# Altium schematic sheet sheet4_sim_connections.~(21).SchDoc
size A3; Author: Mauri Shadi; CompanyName: BFH; DrawnBy: Mauri Shadi; SheetNumber: 1; SheetTotal: 3
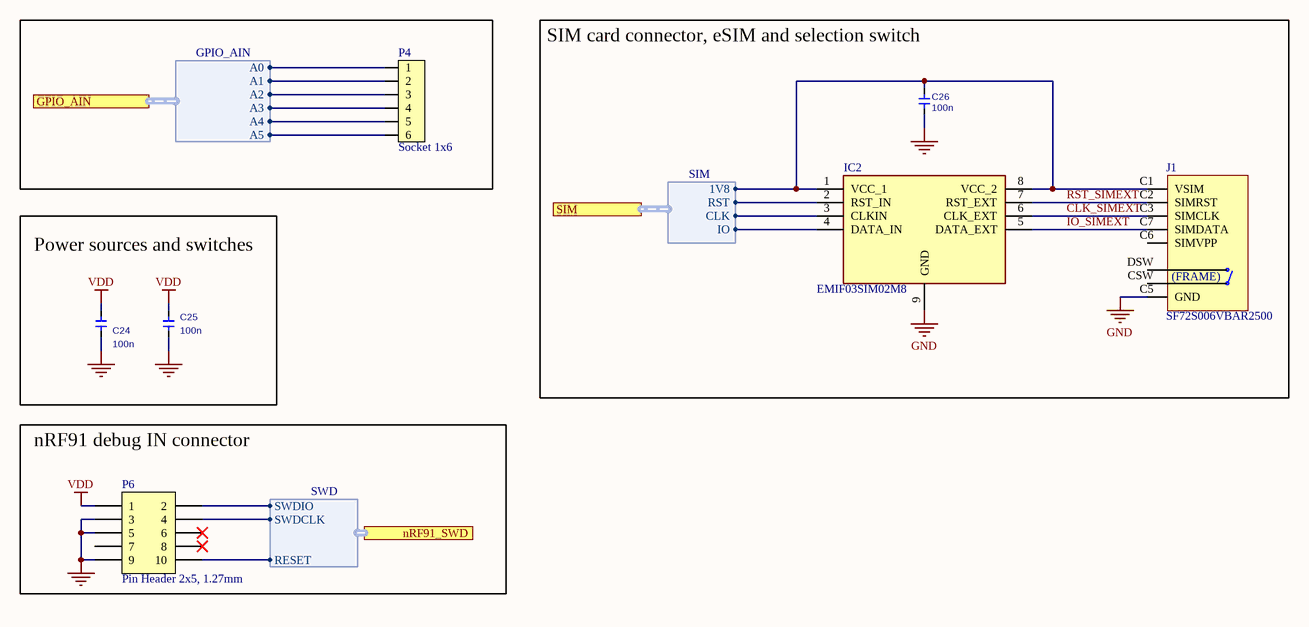
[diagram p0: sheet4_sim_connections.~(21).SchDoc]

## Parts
C24  100n  [0603(1608)C]
C25  100n  [0603(1608)C]
C26  100n  [0603(1608)C]
IC2  EMIF03SIM02M8  [SON40P150X170X60-9N-D]
J1  SF72S006VBAR2500  [SF72S006VBAR2500]
P4  Socket 1x6  [SOCKET_1x6_SMD]
P6  Pin Header 2x5, 1.27mm  [HDR_2x5-SMD-1.27mm-K]

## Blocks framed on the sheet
SIM card connector, eSIM and selection switch: C26 IC2 J1
Power sources and switches: C24 C25
nRF91 debug IN connector: P6

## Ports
GPIO_AIN (harness GPIO_AIN, see sheet2_nRF9160[7C]), nRF91_SWD (harness SWD, see sheet2_nRF9160[7D]), SIM (harness SIM, see sheet2_nRF9160[7C])

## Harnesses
SWD: SWDIO, SWDCLK, RESET
GPIO_AIN: A0, A1, A2, A3, A4, A5
SIM: CLK, IO, 1V8, RST

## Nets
GND: C24.2 C25.1 C26.1 IC2.9(GND) J1.0(GND) J1.C5(GND) P6.3 P6.5 P6.9
VDD: C24.1 C25.2 P6.1
CLK_SIMEXT: IC2.6(CLK_EXT) J1.C3(SIMCLK)
IO_SIMEXT: IC2.5(DATA_EXT) J1.C7(SIMDATA)
RST_SIMEXT: IC2.7(RST_EXT) J1.C2(SIMRST)
NetC26_2: C26.2 IC2.1(VCC_1) IC2.8(VCC_2) J1.C1(VSIM) ; port SIM.1V8
NetIC2_2: IC2.2(RST_IN) ; port SIM.RST
NetIC2_3: IC2.3(CLKIN) ; port SIM.CLK
NetIC2_4: IC2.4(DATA_IN) ; port SIM.IO
NetP4_1: P4.1 ; port GPIO_AIN.A0
NetP4_2: P4.2 ; port GPIO_AIN.A1
NetP4_3: P4.3 ; port GPIO_AIN.A2
NetP4_4: P4.4 ; port GPIO_AIN.A3
NetP4_5: P4.5 ; port GPIO_AIN.A4
NetP4_6: P4.6 ; port GPIO_AIN.A5
NetP6_2: P6.2 ; port nRF91_SWD.SWDIO
NetP6_4: P6.4 ; port nRF91_SWD.SWDCLK
NetP6_10: P6.10 ; port nRF91_SWD.RESET

Not connected (* = marked no-connect by the designer): J1 C6(SIMVPP) CSW DSW; P6 6* 7 8*

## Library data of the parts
C24 C25 = C0603_5_100n_25V: Cer Chip Capacitor / 100n/ +-5%/ 25V; Manufacturer Part Number: CC0603KRX7R8BB104; Manufacturer 1: Yageo; Special Value 1: +-5%; Capacitance: 100nF; Tolerance: 10%; Dielectric: X7R
C26 = C0603_5_100n_25V: Cer Chip Capacitor / 100n/ +-5%/ 25V; Manufacturer 1: Yageo; Manufacturer Part Number: CC0603KRX7R8BB104; Special Value 1: +-5%; Capacitance: 100nF; Tolerance: 10%; Dielectric: X7R
IC2 = EMIF03SIM02M8: Integrated Circuit; Manufacturer_Name: STMicroelectronics
J1 = SF72S006VBAR2500: n 8 (6 + 2) Position Card Connector NANO SIM Surface Mount, Right Angle Gold; Manufacturer: JAE Electronics; Part number IPS: 00000009956; Note: N.A.; Pad Count: 8
P4 = Socket 1x6 SMD: Socket 1x6, 2.54mm (100mil), SMD; Manufacturer: W-CON; Manufacturer Part Number: 2171-106MS0CUNR1; Part number IPS: 00000009964; Note: N.A.; Artikkelnr Noca: 55030001; Pad Count: 6
P6 = Pin Header 2x5 SMD, 1.27mm, KS: Pin Header 2x5, 1.27mm (50mil), SMD, Keying Shroud; Manufacturer: W-CON; Manufacturer Part Number: 3132-10MS0BK00R1; Part number IPS: 00000009968; Note: N.A.; Artikkelnr Noca: 55010009; Pad Count: 10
